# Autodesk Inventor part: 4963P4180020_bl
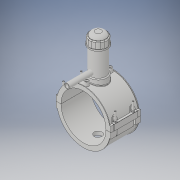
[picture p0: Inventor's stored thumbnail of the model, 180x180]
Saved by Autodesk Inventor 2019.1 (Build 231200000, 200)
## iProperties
Created: 2017-07
Part Number: 4963P4180020_bl
Material: Generic
Document SubType Name: Modeling
Designer: KIM
Density: 1 g/cm^3
Appearance: Default
Author: KIM
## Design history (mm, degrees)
derived "4963P4.ipt"
feature "Solid1::4963P4.ipt" dims "ScaleForDerivedMember" = 10
feature "Solid2::4963P4.ipt" dims "ScaleForDerivedMember" = 10
feature "Solid3::4963P4.ipt" dims "ScaleForDerivedMember" = 10
tag "TaggingFeature1"
body "Solid1"
body "Solid2"
body "Solid3"
other parameters: "B_" = 219 [user parameter], "L_" = 118 [user parameter], "d_t" = 6 [user parameter], "H_2" = 177 [user parameter], "H_" = 125 [user parameter], "d1" = 208.8 [user parameter], "d148" = 2.7 [user parameter], "d160" = 2.7 [user parameter], "d169" = 3.75 [user parameter], "d192" = 8 [user parameter], "d2" = 219 [user parameter], "d3" = 45 [user parameter], "d4" = 118 [user parameter], "d5" = 0 [user parameter], "d6" = 0.1 [user parameter], "d8" = 0 [user parameter], "d19" = 6 [user parameter], "d20" = 6 [user parameter], "d21" = 70.8 [user parameter], "d23" = 0 [user parameter], "d24" = 35.4 [user parameter], "d26" = 0 [user parameter], "d27" = 3 [user parameter], "d28" = 3 [user parameter], "d29" = 3 [user parameter], "d31" = 6 [user parameter], "d32" = 0 [user parameter], "d33" = 0 [user parameter], "d34" = 0.6 [user parameter], "d40" = 108.576 [user parameter], "d41" = 72 [user parameter], "d43" = 0 [user parameter], "d45" = 0 [user parameter], "d47" = 175.2 [user parameter], "d70" = 15 [user parameter], "d72" = 0 [user parameter], "d73" = 6 [user parameter], "d75" = 5 [user parameter], "d76" = 0 [user parameter], "d77" = 9 [user parameter], "d79" = 15 [user parameter], "d80" = 47.2 [user parameter], "d82" = 5 deg [user parameter], "d84" = 4 [user parameter], "d85" = 14 [user parameter], "d86" = 0 [user parameter], "d87" = 3 [user parameter], "d88" = 0 [user parameter], "d89" = 1 [user parameter], "d90" = 1 [user parameter], "d91" = 94.4 [user parameter], "d92" = 0 [user parameter], "d93" = 0.5 [user parameter], "d94" = 94.73684 [user parameter], "d96" = 212.976 [user parameter], "d97" = 2.36 [user parameter], "d98" = 0 [user parameter], "d102" = 1.8 [user parameter], "d120" = 140 deg [user parameter], "d121" = 24.228 [user parameter], "d122" = 20 deg [user parameter], "d123" = 417.6 [user parameter], "d124" = 125.28 [user parameter], "d126" = 0 [user parameter], "d143" = 185.4 [user parameter], "d145" = 22.15385 [user parameter], "d149" = 2.7 [user parameter], "d150" = 24.36923 [user parameter], "d153" = 118 [user parameter], "d154" = 0 [user parameter], "d156" = 104.4 [user parameter], "d157" = 160 deg [user parameter], "d159" = 5.76 [user parameter], "d161" = 2.7 [user parameter], "d162" = 70.8 [user parameter], "d163" = 0 [user parameter], "d167" = 18 [user parameter], "d168" = 101.85366 [user parameter], "d170" = 3.75 [user parameter], "d172" = 0 [user parameter], "d173" = 1 [user parameter], "d176" = 20 deg [user parameter], "d177" = 12.6 [user parameter], "d178" = 28.8 [user parameter], "d180" = 0 [user parameter], "d183" = 11.52 [user parameter], "d184" = 10.08 [user parameter], "d185" = 38.35 [user parameter], "d186" = 38.35 [user parameter], "d187" = 104.4 [user parameter], "d188" = 8.64 [user parameter], "d189" = 12.6 [user parameter], "d190" = 0 [user parameter], "d191" = 156.6 [user parameter], "d193" = 8 [user parameter], "d194" = 4.13 [user parameter], "d195" = 90 deg [user parameter], "d197" = 0 [user parameter], "d199" = 0 [user parameter], "d200" = 14.4 [user parameter], "d202" = 0 [user parameter], "d203" = 177 [user parameter], "d204" = 68.4 [user parameter], "d205" = 50.4 [user parameter], "d206" = 61.2 [user parameter], "d207" = 132.75 [user parameter], "d208" = 138.06 [user parameter], "d209" = 164.61 [user parameter], "d210" = 61.92 [user parameter], "d211" = 72 [user parameter], "d212" = 57.6 [user parameter], "d213" = 36 [user parameter], "d216" = 0 [user parameter], "d217" = 18 [user parameter], "d218" = 18 [user parameter], "d219" = 3.6 [user parameter], "d224" = 0 [user parameter], "d227" = 16 [user parameter], "d228" = 125 [user parameter], "d230" = 3.6 [user parameter]
